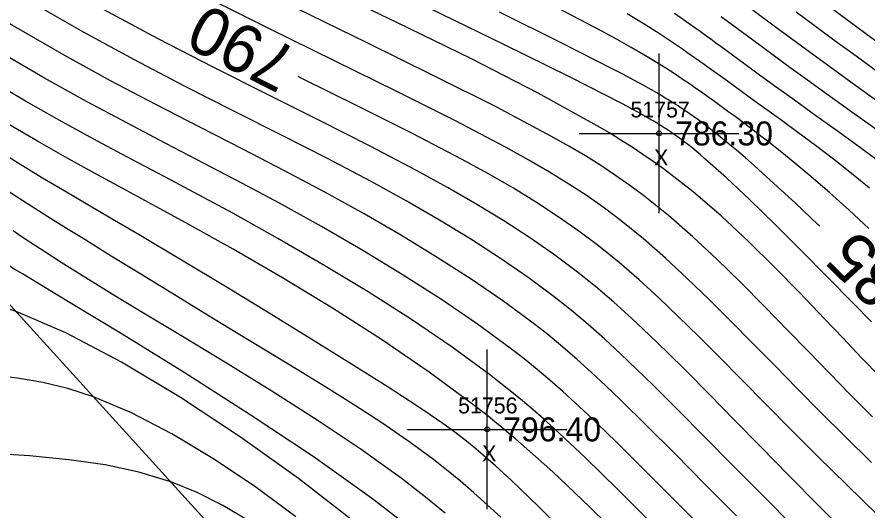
# Model space of a CAD drawing. Extents: x 1378535 to 1380697, y 997729 to 1000024.
# Drawn here: x 1379799.5 to 1379852.8, y 998744.2 to 998775.1 of the extents above; entities that cross this region are included whole.
import ezdxf

# ---------------------------------------------------------------- set-up
doc = ezdxf.new("R2010")
doc.units = 0
for name, color, linetype in [('RD_DTM_BkLn2', 7, 'Continuous'), ('RD_DTM_Major1', 7, 'Continuous'), ('RD_DTM_Major1_Lbl', 7, 'Continuous'), ('RD_DTM_Minor1', 7, 'Continuous'), ('RD_EX_Misc', 7, 'Continuous'), ('RD_EX_Misc_txCode', 7, 'Continuous'), ('RD_EX_TX_Misc_ELEV', 7, 'Continuous'), ('RD_SMD_Locator', 7, 'Continuous')]:
    doc.layers.add(name, color=color, linetype=linetype)

msp = doc.modelspace()

# ---------------------------------------------------------------- linework, layer by layer
at = {"layer": 'RD_DTM_BkLn2'}
msp.add_lwpolyline([(1379855.611, 998702.628), (1379815.746, 998738.674), (1379770.168, 998788.836), (1379745.983, 998819.459), (1379725.877, 998843.791)], dxfattribs=at)
at = {"layer": 'RD_DTM_Major1'}
for points in [[(1379854.093, 998769.295), (1379851.993, 998770.804), (1379850.677, 998771.758), (1379849.445, 998772.658), (1379848.286, 998773.509), (1379847.192, 998774.318), (1379846.152, 998775.09), (1379845.156, 998775.83), (1379844.692, 998776.175), (1379844.231, 998776.518), (1379843.771, 998776.859), (1379842.837, 998777.547), (1379842.356, 998777.9), (1379841.087, 998778.817), (1379839.716, 998779.782), (1379838.237, 998780.789), (1379836.639, 998781.831), (1379834.916, 998782.901), (1379834.804, 998782.966)], [(1379849.739, 998762.015), (1379849.644, 998762.105), (1379848.218, 998763.45), (1379846.873, 998764.695), (1379845.643, 998765.801), (1379845.062, 998766.31), (1379844.518, 998766.776), (1379844.008, 998767.203), (1379843.529, 998767.594), (1379843.077, 998767.953), (1379842.649, 998768.284), (1379842.372, 998768.494), (1379842.1, 998768.694), (1379841.831, 998768.889), (1379841.56, 998769.078), (1379841.285, 998769.266), (1379841.001, 998769.454), (1379840.861, 998769.545), (1379840.718, 998769.637), (1379840.57, 998769.73), (1379840.419, 998769.824), (1379840.263, 998769.921), (1379840.101, 998770.019), (1379839.67, 998770.275), (1379839.195, 998770.549), (1379838.671, 998770.844), (1379838.09, 998771.162), (1379837.447, 998771.506), (1379836.735, 998771.88), (1379833.581, 998773.483), (1379829.686, 998775.416)], [(1379839.179, 998743.452), (1379837.08, 998745.549), (1379835.056, 998747.524), (1379833.107, 998749.346), (1379832.447, 998749.938), (1379831.789, 998750.513), (1379831.128, 998751.075), (1379830.456, 998751.629), (1379829.767, 998752.179), (1379829.055, 998752.73), (1379826.717, 998754.436), (1379824.161, 998756.168), (1379821.449, 998757.9), (1379818.64, 998759.605), (1379815.798, 998761.256), (1379812.982, 998762.825), (1379810.859, 998763.968), (1379808.759, 998765.079), (1379806.65, 998766.191), (1379804.504, 998767.336), (1379802.289, 998768.546), (1379799.975, 998769.855), (1379796.39, 998771.979)], [(1379853.386, 998743.932), (1379851.433, 998745.823), (1379849.624, 998747.605), (1379847.938, 998749.288), (1379846.354, 998750.885), (1379844.852, 998752.405), (1379843.413, 998753.859), (1379842.146, 998755.126), (1379840.901, 998756.348), (1379839.665, 998757.525), (1379838.424, 998758.657), (1379837.165, 998759.744), (1379835.877, 998760.786), (1379834.644, 998761.713), (1379833.356, 998762.614), (1379831.996, 998763.502), (1379830.546, 998764.389), (1379828.988, 998765.289), (1379827.305, 998766.213), (1379824.231, 998767.816), (1379820.853, 998769.514), (1379817.256, 998771.295), (1379817.068, 998771.389)], [(1379823.664, 998743.438), (1379821.655, 998744.991), (1379817.998, 998747.6), (1379814.005, 998750.259), (1379809.931, 998752.849), (1379806.033, 998755.254), (1379802.566, 998757.355), (1379799.787, 998759.037), (1379799.261, 998759.359), (1379798.783, 998759.653), (1379798.349, 998759.921), (1379797.956, 998760.165), (1379797.599, 998760.387), (1379797.276, 998760.589), (1379797.104, 998760.696)]]:
    msp.add_lwpolyline(points, dxfattribs=at)
at = {"layer": 'RD_DTM_Minor1'}
for points in [[(1379853.546, 998752.56), (1379852.364, 998753.785), (1379851.198, 998755.004), (1379850.031, 998756.229), (1379848.49, 998757.841), (1379846.907, 998759.461), (1379845.273, 998761.069), (1379843.577, 998762.643), (1379841.807, 998764.161), (1379839.953, 998765.603), (1379839.314, 998766.063), (1379838.661, 998766.515), (1379837.987, 998766.963), (1379837.289, 998767.409), (1379836.561, 998767.858), (1379835.8, 998768.311), (1379832.104, 998770.352), (1379827.872, 998772.511), (1379823.291, 998774.756), (1379818.547, 998777.055)], [(1379852.971, 998747.232), (1379851.333, 998748.844), (1379849.793, 998750.383), (1379848.329, 998751.862), (1379846.923, 998753.292), (1379845.555, 998754.684), (1379844.175, 998756.079), (1379842.808, 998757.438), (1379841.444, 998758.753), (1379840.076, 998760.017), (1379838.696, 998761.22), (1379837.296, 998762.356), (1379836.246, 998763.146), (1379835.162, 998763.909), (1379834.025, 998764.656), (1379832.816, 998765.401), (1379831.515, 998766.158), (1379830.105, 998766.938), (1379826.881, 998768.625), (1379823.252, 998770.442), (1379819.343, 998772.366), (1379815.278, 998774.373), (1379811.182, 998776.439)], [(1379848.162, 998743.157), (1379846.167, 998745.151), (1379844.292, 998747.042), (1379842.528, 998748.828), (1379840.865, 998750.504), (1379839.296, 998752.067), (1379838.264, 998753.075), (1379837.254, 998754.037), (1379836.249, 998754.962), (1379835.233, 998755.858), (1379834.186, 998756.736), (1379833.093, 998757.603), (1379831.475, 998758.803), (1379829.736, 998760.002), (1379827.881, 998761.2), (1379825.911, 998762.4), (1379823.83, 998763.602), (1379821.641, 998764.806), (1379818.893, 998766.252), (1379816.016, 998767.72), (1379813.029, 998769.228), (1379809.954, 998770.792), (1379806.81, 998772.431), (1379803.619, 998774.16), (1379800.108, 998776.163)], [(1379852.821, 998761.882), (1379851.591, 998763.017), (1379850.376, 998764.108), (1379849.19, 998765.137), (1379848.312, 998765.87), (1379847.464, 998766.557), (1379846.648, 998767.2), (1379845.869, 998767.8), (1379845.129, 998768.358), (1379844.433, 998768.876), (1379843.988, 998769.205), (1379843.56, 998769.519), (1379843.144, 998769.821), (1379842.735, 998770.115), (1379842.328, 998770.403), (1379841.92, 998770.688), (1379841.722, 998770.825), (1379841.521, 998770.962), (1379841.317, 998771.1), (1379841.108, 998771.24), (1379840.894, 998771.382), (1379840.674, 998771.527), (1379840.088, 998771.904), (1379839.443, 998772.306), (1379838.729, 998772.736), (1379837.933, 998773.2), (1379837.043, 998773.701), (1379836.049, 998774.244), (1379832.935, 998775.869)], [(1379853.712, 998773.269), (1379852.623, 998774.065), (1379851.503, 998774.891), (1379850.361, 998775.74)], [(1379851.661, 998742.537), (1379849.666, 998744.531), (1379847.8, 998746.418), (1379846.05, 998748.201), (1379844.4, 998749.885), (1379842.836, 998751.477), (1379841.345, 998752.98), (1379840.201, 998754.115), (1379839.079, 998755.203), (1379837.962, 998756.249), (1379836.836, 998757.26), (1379835.683, 998758.24), (1379834.49, 998759.196), (1379833.065, 998760.259), (1379831.557, 998761.306), (1379829.955, 998762.346), (1379828.249, 998763.385), (1379826.43, 998764.434), (1379824.486, 998765.501), (1379821.567, 998767.028), (1379818.438, 998768.61), (1379815.149, 998770.254), (1379811.749, 998771.965), (1379808.29, 998773.748), (1379804.821, 998775.608)], [(1379853.036, 998750.084), (1379851.653, 998751.478), (1379850.322, 998752.834), (1379849.026, 998754.165), (1379847.746, 998755.483), (1379846.27, 998756.995), (1379844.787, 998758.487), (1379843.293, 998759.944), (1379841.784, 998761.348), (1379840.257, 998762.682), (1379838.705, 998763.93), (1379837.841, 998764.574), (1379836.954, 998765.197), (1379836.031, 998765.808), (1379835.057, 998766.416), (1379834.019, 998767.031), (1379832.902, 998767.664), (1379829.507, 998769.466), (1379825.613, 998771.421), (1379821.382, 998773.494), (1379816.973, 998775.653)], [(1379852.985, 998756.024), (1379851.864, 998757.17), (1379850.233, 998758.832), (1379848.581, 998760.501), (1379846.946, 998762.126), (1379845.37, 998763.659), (1379843.892, 998765.048), (1379842.551, 998766.244), (1379842.268, 998766.486), (1379841.992, 998766.715), (1379841.722, 998766.935), (1379841.455, 998767.145), (1379841.191, 998767.347), (1379840.926, 998767.543), (1379840.746, 998767.672), (1379840.565, 998767.799), (1379840.381, 998767.925), (1379840.193, 998768.05), (1379840.001, 998768.175), (1379839.804, 998768.3), (1379839.707, 998768.36), (1379839.609, 998768.42), (1379839.509, 998768.481), (1379839.407, 998768.543), (1379839.304, 998768.604), (1379839.199, 998768.666), (1379838.926, 998768.825), (1379838.641, 998768.987), (1379838.341, 998769.154), (1379838.026, 998769.327), (1379837.695, 998769.505), (1379837.347, 998769.69), (1379834.063, 998771.364), (1379829.949, 998773.385), (1379825.274, 998775.658)], [(1379852.866, 998764.404), (1379851.738, 998765.318), (1379850.6, 998766.208), (1379849.468, 998767.067), (1379848.359, 998767.889), (1379847.292, 998768.67), (1379845.64, 998769.87), (1379844.438, 998770.743), (1379843.867, 998771.157), (1379843.309, 998771.56), (1379842.759, 998771.955), (1379842.496, 998772.143), (1379841.966, 998772.519), (1379841.42, 998772.901), (1379841.137, 998773.096), (1379840.389, 998773.603), (1379839.574, 998774.138), (1379838.675, 998774.707), (1379837.677, 998775.314)], [(1379853.829, 998765.783), (1379852.376, 998766.859), (1379850.921, 998767.916), (1379849.502, 998768.937), (1379848.155, 998769.905), (1379847.302, 998770.52), (1379846.493, 998771.107), (1379845.721, 998771.669), (1379844.98, 998772.209), (1379844.264, 998772.732), (1379843.567, 998773.24), (1379843.237, 998773.481), (1379842.908, 998773.72), (1379842.578, 998773.959), (1379842.244, 998774.2), (1379841.904, 998774.443), (1379841.557, 998774.69), (1379840.642, 998775.33)], [(1379853.38, 998771.668), (1379852.017, 998772.654), (1379850.714, 998773.604), (1379849.467, 998774.521), (1379848.269, 998775.407)], [(1379844.522, 998743.883), (1379842.541, 998745.876), (1379840.672, 998747.76), (1379838.911, 998749.521), (1379837.257, 998751.146), (1379836.34, 998752.024), (1379835.442, 998752.862), (1379834.546, 998753.669), (1379833.636, 998754.455), (1379832.697, 998755.23), (1379831.711, 998756.004), (1379829.888, 998757.344), (1379827.905, 998758.702), (1379825.781, 998760.068), (1379823.537, 998761.434), (1379821.196, 998762.789), (1379818.777, 998764.126), (1379816.217, 998765.482), (1379813.594, 998766.835), (1379810.905, 998768.209), (1379808.146, 998769.631), (1379805.315, 998771.127), (1379802.408, 998772.721), (1379798.854, 998774.77)], [(1379853.539, 998767.883), (1379851.748, 998769.164), (1379850.044, 998770.385), (1379848.97, 998771.16), (1379847.956, 998771.896), (1379846.997, 998772.596), (1379846.083, 998773.267), (1379845.208, 998773.911), (1379844.363, 998774.534), (1379843.966, 998774.827), (1379843.572, 998775.117)], [(1379842.905, 998742.594), (1379840.827, 998744.684), (1379838.851, 998746.669), (1379836.979, 998748.525), (1379835.211, 998750.227), (1379834.414, 998750.97), (1379833.628, 998751.683), (1379832.841, 998752.373), (1379832.041, 998753.049), (1379831.215, 998753.718), (1379830.351, 998754.391), (1379828.301, 998755.889), (1379826.051, 998757.419), (1379823.644, 998758.961), (1379821.121, 998760.495), (1379818.525, 998762.002), (1379815.895, 998763.462), (1379813.543, 998764.719), (1379811.178, 998765.953), (1379808.78, 998767.196), (1379806.328, 998768.479), (1379803.802, 998769.833), (1379801.182, 998771.289), (1379797.593, 998773.38)], [(1379837.608, 998742.186), (1379835.316, 998744.447), (1379833.009, 998746.63), (1379830.673, 998748.704), (1379830.249, 998749.063), (1379829.822, 998749.418), (1379829.393, 998749.771), (1379828.959, 998750.12), (1379828.52, 998750.468), (1379828.076, 998750.815), (1379825.272, 998752.885), (1379822.292, 998754.918), (1379819.206, 998756.891), (1379816.085, 998758.782), (1379813, 998760.571), (1379810.02, 998762.235), (1379808.146, 998763.256), (1379806.315, 998764.244), (1379804.492, 998765.233), (1379802.644, 998766.252), (1379800.737, 998767.334), (1379798.738, 998768.509)], [(1379834.031, 998742.588), (1379832.129, 998744.466), (1379830.411, 998746.113), (1379829.915, 998746.574), (1379829.436, 998747.009), (1379828.971, 998747.421), (1379828.515, 998747.814), (1379828.064, 998748.19), (1379827.614, 998748.554), (1379826.881, 998749.118), (1379826.126, 998749.668), (1379825.337, 998750.217), (1379824.502, 998750.777), (1379823.61, 998751.358), (1379822.647, 998751.974), (1379820.416, 998753.383), (1379817.923, 998754.935), (1379815.257, 998756.575), (1379812.506, 998758.248), (1379809.758, 998759.899), (1379807.102, 998761.473), (1379805.551, 998762.381), (1379804.041, 998763.263), (1379802.549, 998764.14), (1379801.049, 998765.035), (1379799.516, 998765.972), (1379797.925, 998766.972)], [(1379829.757, 998743.799), (1379828.912, 998744.582), (1379828.074, 998745.333), (1379827.228, 998746.06), (1379826.363, 998746.77), (1379825.466, 998747.469), (1379823.936, 998748.586), (1379822.305, 998749.7), (1379820.59, 998750.814), (1379818.806, 998751.932), (1379816.971, 998753.058), (1379815.1, 998754.195), (1379813.106, 998755.407), (1379811.113, 998756.622), (1379809.143, 998757.826), (1379807.219, 998759.006), (1379805.361, 998760.148), (1379803.594, 998761.239), (1379802.562, 998761.878), (1379801.56, 998762.504), (1379800.574, 998763.127), (1379799.593, 998763.757), (1379798.604, 998764.406)], [(1379826.27, 998744.058), (1379824.948, 998745.141), (1379823.525, 998746.24), (1379821.002, 998748.046), (1379818.265, 998749.874), (1379815.418, 998751.686), (1379812.568, 998753.443), (1379809.819, 998755.105), (1379807.276, 998756.635), (1379805.852, 998757.498), (1379804.538, 998758.301), (1379803.33, 998759.049), (1379802.218, 998759.748), (1379801.197, 998760.403), (1379800.258, 998761.019), (1379799.72, 998761.38), (1379799.203, 998761.733)], [(1379820.475, 998743.588), (1379817.087, 998746.213), (1379813.444, 998748.82), (1379809.7, 998751.29), (1379806.007, 998753.503), (1379802.52, 998755.337), (1379799.392, 998756.672), (1379798.313, 998757.031), (1379797.282, 998757.31), (1379796.271, 998757.525), (1379795.253, 998757.686), (1379794.201, 998757.807), (1379793.085, 998757.9), (1379789.577, 998758.083), (1379785.535, 998758.196), (1379781.108, 998758.28), (1379776.447, 998758.377), (1379771.704, 998758.53)], [(1379816.928, 998743.832), (1379814.339, 998745.734), (1379811.729, 998747.481), (1379809.145, 998749.028), (1379806.632, 998750.33), (1379804.236, 998751.341), (1379802.644, 998751.858), (1379801.076, 998752.238), (1379799.474, 998752.508), (1379797.783, 998752.696), (1379795.946, 998752.828), (1379793.907, 998752.933), (1379788.102, 998753.169), (1379781.084, 998753.403), (1379773.096, 998753.636), (1379764.38, 998753.867)], [(1379813.933, 998743.587), (1379812.35, 998744.531), (1379810.739, 998745.339), (1379809.081, 998746.01), (1379807.087, 998746.616), (1379804.973, 998747.068), (1379802.703, 998747.397), (1379800.243, 998747.633), (1379797.559, 998747.808), (1379794.617, 998747.951), (1379788.576, 998748.201), (1379781.735, 998748.448), (1379774.253, 998748.695), (1379766.29, 998748.94)]]:
    msp.add_lwpolyline(points, dxfattribs=at)
at = {"layer": 'RD_EX_Misc'}
for p, q in [((1379839.676, 998762.824), (1379839.676, 998772.824)), ((1379834.676, 998767.824), (1379844.676, 998767.824)), ((1379828.906, 998744.296), (1379828.906, 998754.296)), ((1379823.906, 998749.296), (1379833.906, 998749.296))]:
    msp.add_line(p, q, dxfattribs=at)
at = {"layer": 'RD_SMD_Locator'}
for centre in [(1379839.676, 998767.824), (1379828.906, 998749.296)]:
    msp.add_circle(centre, 0.15, dxfattribs=at)

# ---------------------------------------------------------------- texts
at = {"layer": 'RD_DTM_Major1_Lbl'}
for s, rotation, p in [('790', 153.1335, (1379817.198, 998772.977)), ('785', 135.6143, (1379856.808, 998757.232))]:
    msp.add_text(s, height=3, rotation=rotation, dxfattribs=at).set_placement(p)
at = {"layer": 'RD_EX_Misc_txCode'}
for s, p in [('51757', (1379837.881, 998768.824)), ('X', (1379839.361, 998765.824)), ('51756', (1379827.087, 998750.296)), ('X', (1379828.591, 998747.296))]:
    msp.add_text(s, height=1, dxfattribs=at).set_placement(p)
at = {"layer": 'RD_EX_TX_Misc_ELEV'}
for s, p in [('786.30', (1379840.676, 998767.074)), ('796.40', (1379829.906, 998748.546))]:
    msp.add_text(s, height=1.5, dxfattribs=at).set_placement(p)

doc.saveas('drawing.dxf')
